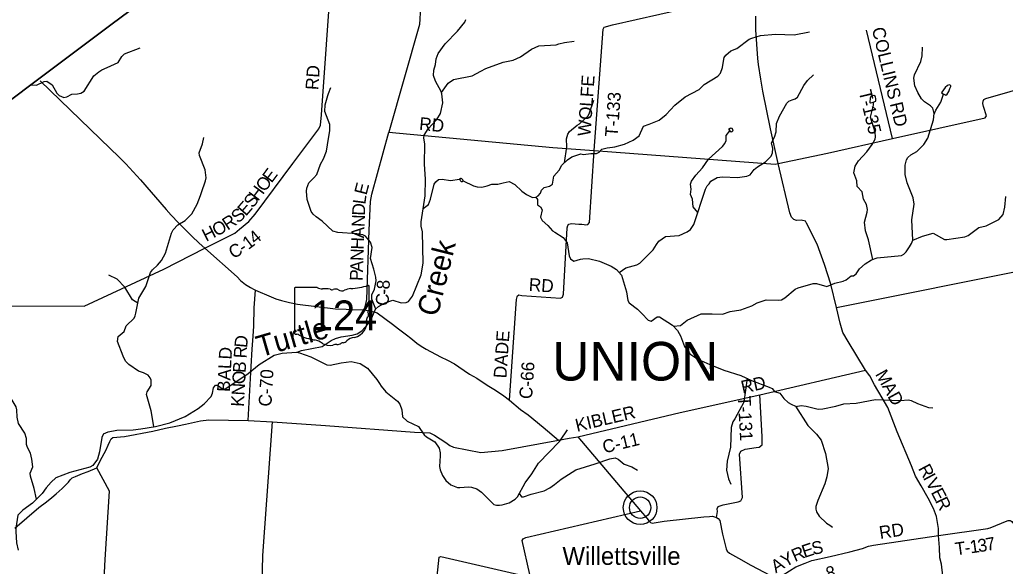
# Model space of a CAD drawing. Extents: x 1525783 to 1900577, y 218250 to 627376.
# Drawn here: x 1612574 to 1635582, y 457419 to 470168 of the extents above; entities that cross this region are included whole.
import ezdxf

# ---------------------------------------------------------------- set-up
doc = ezdxf.new("R2010")
doc.units = 0
for name, color, linetype in [('GM_X_Adjacent_County', 7, 'Continuous'), ('GM_X_County', 7, 'Continuous'), ('GM_X_County_Road', 7, 'Continuous'), ('GM_X_County_Road_Text', 7, 'Continuous'), ('GM_X_Minor_Lake', 7, 'Continuous'), ('GM_X_Minor_River', 7, 'Continuous'), ('GM_X_Minor_River_Text', 7, 'Continuous'), ('GM_X_State_Location', 7, 'Continuous'), ('GM_X_State_Route', 7, 'Continuous'), ('GM_X_State_Shield', 7, 'Continuous'), ('GM_X_Township', 7, 'Continuous'), ('GM_X_Township_Road', 7, 'Continuous'), ('GM_X_Township_Road_Text', 7, 'Continuous'), ('GM_X_Township_ROW', 7, 'Continuous'), ('GM_X_Township_Text', 7, 'Continuous'), ('GM_X_Unincorporated', 7, 'Continuous'), ('GM_X_Unincorporated_Location', 7, 'Continuous'), ('GM_X_Unincorporated_Text', 7, 'Continuous')]:
    doc.layers.add(name, color=color, linetype=linetype)

msp = doc.modelspace()

# ---------------------------------------------------------------- linework, layer by layer
at = {"layer": 'GM_X_Adjacent_County'}
msp.add_lwpolyline([(1655741, 500852), (1648788, 495779), (1648023, 495203), (1647133, 494533), (1640676, 489672), (1638042, 487688), (1635644, 485883), (1633819, 484508), (1633505, 484272), (1633248, 484078), (1631413, 482696), (1628958, 480847), (1628919, 480818), (1621997, 475474), (1621966, 475451), (1620523, 474378), (1618604, 472952), (1614700, 470050), (1612987, 468763), (1608261, 465210)], dxfattribs=at)
at = {"layer": 'GM_X_County'}
msp.add_lwpolyline([(1608261, 465210), (1612987, 468763), (1614700, 470050), (1618604, 472952), (1620523, 474378), (1621966, 475451), (1621997, 475474), (1628919, 480818), (1628958, 480847), (1631413, 482696), (1633248, 484078), (1633505, 484272), (1633819, 484508), (1635644, 485883), (1638042, 487688), (1640676, 489672), (1647133, 494533), (1648023, 495203), (1648788, 495779), (1655741, 500852)], dxfattribs=at)
at = {"layer": 'GM_X_County_Road'}
for points in [[(1622004, 471684), (1621903, 470055), (1621187, 467545)], [(1616894, 464836), (1617238, 465007), (1617593, 465191), (1617706, 465283), (1617919, 465465), (1618070, 465630), (1618950, 466813), (1619555, 467622), (1619599, 467705), (1619622, 467949), (1619849, 471240)], [(1630283, 466815), (1630102, 467622), (1629921, 468502), (1629876, 468780), (1629821, 469126), (1629805, 469261), (1629760, 469933), (1629755, 470250)], [(1630283, 466815), (1631433, 467057), (1632947, 467397), (1635111, 467882), (1635142, 467924), (1635076, 468146), (1635061, 468212), (1635063, 468268), (1635080, 468310), (1635129, 468331), (1637455, 468999)], [(1620622, 463404), (1620675, 463645), (1620734, 465258), (1620762, 465929), (1620796, 466099), (1621187, 467545), (1625016, 467185), (1625986, 467115), (1630208, 466799), (1630283, 466815)], [(1624010, 461291), (1624166, 463538), (1624175, 463644), (1624178, 463674), (1624183, 463702), (1624191, 463730), (1624226, 463747), (1624296, 463739), (1625201, 463673), (1625244, 463698), (1625270, 463763), (1625357, 465316), (1625369, 465370), (1625391, 465400), (1625454, 465416), (1625626, 465399), (1625694, 465398), (1625748, 465388), (1625792, 465385), (1625840, 465392), (1625877, 465437), (1625986, 467115)], [(1634156, 456927), (1634091, 457468), (1634051, 457616), (1634047, 457854), (1634025, 458139), (1634023, 458298), (1633974, 458583), (1633905, 458766), (1633783, 459005), (1633615, 459292), (1633487, 459524), (1633389, 459761), (1633061, 460556), (1632838, 461121), (1632704, 461351), (1632531, 461650), (1632419, 461865), (1632316, 461996), (1631915, 462664), (1631789, 462870), (1631728, 463092), (1631640, 463455), (1631508, 463999), (1631362, 464458), (1631188, 464934), (1630945, 465419), (1630916, 465466), (1630817, 465495), (1630708, 465487), (1630645, 465507), (1630588, 465559), (1630551, 465664), (1630283, 466815)], [(1608202, 458990), (1608203, 458990), (1608370, 458987), (1609398, 458988), (1609760, 458989), (1609917, 458994), (1610645, 459107), (1610906, 459152), (1611190, 459203), (1611367, 459238), (1611441, 459254), (1611469, 459292), (1611494, 459398), (1611652, 461938), (1611750, 463493), (1614078, 463489), (1615942, 464351), (1616894, 464836)], [(1617906, 460822), (1617979, 462079), (1617998, 462483), (1618026, 462783), (1618040, 463017), (1618046, 463448), (1618078, 463862)], [(1625600, 460439), (1627995, 461006), (1629849, 461416), (1632316, 461996)], [(1612458, 458311), (1613021, 458786), (1613200, 458924), (1613322, 459027), (1613427, 459109), (1613566, 459235), (1613714, 459380), (1613749, 459432), (1613795, 459480), (1613877, 459514), (1614038, 459583), (1614172, 459627), (1614377, 459716), (1614460, 459892), (1614588, 460121), (1614641, 460246), (1614678, 460331), (1614709, 460394), (1614746, 460421), (1615017, 460448), (1615683, 460569), (1615980, 460643), (1616258, 460696), (1616441, 460735), (1616794, 460808), (1616991, 460837), (1617906, 460822), (1618474, 460787), (1619714, 460700), (1621787, 460547), (1622151, 460529), (1622258, 460476), (1622520, 460303), (1622614, 460233), (1622701, 460200), (1623337, 460071), (1623839, 460122), (1625153, 460358)]]:
    msp.add_lwpolyline(points, dxfattribs=at)
at = {"layer": 'GM_X_Minor_Lake'}
for points in [[(1634103, 468477), (1634096, 468462), (1634133, 468441)], [(1634133, 468441), (1634160, 468424), (1634190, 468409), (1634224, 468433), (1634261, 468492), (1634286, 468562), (1634297, 468580), (1634309, 468612), (1634308, 468636), (1634268, 468646), (1634231, 468631), (1634179, 468588), (1634140, 468532), (1634103, 468477)], [(1632420, 468247), (1632419, 468237), (1632428, 468230), (1632434, 468231), (1632494, 468247)], [(1632494, 468247), (1632556, 468267), (1632563, 468318), (1632554, 468375), (1632510, 468403), (1632466, 468396), (1632442, 468378), (1632429, 468337), (1632420, 468247)], [(1629154, 467574), (1629182, 467552), (1629206, 467559), (1629220, 467573), (1629226, 467603), (1629205, 467632), (1629175, 467638), (1629157, 467632), (1629122, 467607)], [(1629122, 467607), (1629135, 467597), (1629154, 467574)], [(1622923, 466412), (1622918, 466430), (1622896, 466454), (1622880, 466464), (1622866, 466465), (1622850, 466459), (1622842, 466449), (1622853, 466425), (1622863, 466411), (1622883, 466398), (1622911, 466396)], [(1622911, 466396), (1622923, 466412)]]:
    msp.add_lwpolyline(points, dxfattribs=at)
at = {"layer": 'GM_X_Minor_River'}
for points in [[(1619049, 462411), (1619153, 462449), (1619637, 462542), (1619845, 462687), (1619946, 462733), (1620075, 462773), (1620332, 462807), (1620450, 462844), (1620560, 462908), (1620716, 463082), (1620790, 463201), (1620880, 463416), (1620949, 463481), (1621108, 463566), (1621288, 463630), (1621481, 463566), (1621597, 463571), (1621648, 463596), (1621742, 463717), (1621944, 464214), (1621990, 464488), (1621974, 465221), (1621946, 465349), (1621945, 465456), (1622037, 466057), (1622047, 466451), (1622025, 466800), (1622030, 467267), (1622010, 467413), (1622015, 467479), (1622110, 467624), (1622313, 467843), (1622396, 467980), (1622450, 468233), (1622431, 468438), (1622414, 468496), (1622283, 468737), (1622233, 468870), (1622239, 468990), (1622280, 469127), (1622298, 469257), (1622344, 469384), (1622503, 469608), (1622794, 469904), (1622966, 470110), (1622989, 470173)], [(1622923, 466413), (1623170, 466296), (1623253, 466268), (1623359, 466265), (1623484, 466291), (1623595, 466335), (1623737, 466331), (1623862, 466363), (1623998, 466391), (1624133, 466323), (1624297, 466170), (1624404, 466092), (1624543, 466022), (1624621, 466027), (1624676, 466060), (1624729, 466123), (1624758, 466189), (1624817, 466254), (1624943, 466288), (1625008, 466329), (1625045, 466517), (1625171, 466657), (1625227, 466774), (1625358, 466900), (1625463, 466971), (1625670, 467038), (1625736, 467025), (1625910, 467048), (1626036, 467044), (1626103, 467081), (1626166, 467146), (1626287, 467182), (1626413, 467198), (1626463, 467206), (1626691, 467262), (1626896, 467355), (1627034, 467463), (1627136, 467684), (1627270, 467728), (1627504, 467828), (1627665, 467958), (1627870, 468177), (1628111, 468367), (1628432, 468541), (1628556, 468657), (1628870, 468848), (1628935, 468921), (1628979, 469051), (1628988, 469105), (1629021, 469285), (1629060, 469340), (1629171, 469442), (1629316, 469496), (1629606, 469714), (1629665, 469739), (1629864, 469802), (1630221, 469835), (1630651, 469816), (1631010, 469888)], [(1622421, 468470), (1622577, 468688), (1622698, 468774), (1623138, 468861), (1623340, 468966), (1623453, 469029), (1623858, 469181), (1624097, 469227), (1624264, 469304), (1624521, 469485), (1624695, 469562), (1625100, 469584), (1625156, 469603), (1625289, 469639), (1625519, 469667)], [(1614613, 469050), (1614869, 469173), (1614957, 469310), (1615022, 469369), (1615389, 469509)], [(1633420, 465025), (1633397, 465500), (1633451, 465868), (1633433, 466012), (1633295, 466367), (1633244, 466554), (1633243, 466774), (1633273, 466900), (1633304, 466951), (1633375, 467014), (1633517, 467098), (1633679, 467258), (1633776, 467403), (1633905, 467833), (1633925, 467979), (1633893, 468106), (1633834, 468163), (1633695, 468253), (1633628, 468324), (1633538, 468470), (1633469, 468625), (1633447, 468803), (1633465, 468883), (1633614, 469195), (1633642, 469329), (1633649, 469525)], [(1612838, 468649), (1612969, 468641), (1613143, 468731), (1613207, 468733), (1613330, 468649), (1613438, 468453), (1613493, 468399), (1613605, 468357), (1613673, 468370), (1613788, 468431), (1613926, 468437), (1613999, 468455), (1614077, 468498), (1614306, 468857), (1614424, 468954), (1614494, 468997), (1614613, 469050)], [(1626566, 464274), (1626721, 464382), (1626980, 464448), (1627051, 464491), (1627362, 464804), (1627436, 464927), (1627492, 465005), (1627650, 465114), (1627970, 465135), (1628156, 465223), (1628233, 465278), (1628313, 465394), (1628584, 466213), (1628621, 466291), (1628668, 466342), (1628707, 466402), (1628854, 466487), (1628977, 466506), (1629329, 466484), (1629550, 466515), (1629628, 466552), (1629722, 466672), (1629795, 466737), (1629981, 466856), (1630114, 466989), (1630151, 467060), (1630156, 467166), (1630127, 467299), (1630195, 467428), (1630235, 467553), (1630242, 467744), (1630312, 467915), (1630479, 468221), (1630532, 468266), (1630607, 468299), (1630677, 468326), (1630728, 468361), (1630876, 468631), (1630968, 468750), (1631104, 468884)], [(1620885, 463420), (1620795, 463647), (1620795, 463753), (1620859, 463885), (1620892, 464078), (1620886, 464166), (1620839, 464353), (1620765, 464601), (1620802, 464851), (1620763, 464981), (1620647, 465119), (1620583, 465154), (1620441, 465175), (1620003, 465202), (1619880, 465234), (1619633, 465468), (1619494, 465568), (1619421, 465633), (1619376, 465692), (1619287, 465976), (1619272, 466172), (1619279, 466238), (1619323, 466362), (1619439, 466478), (1619512, 466561), (1619596, 466800), (1619668, 466923), (1619735, 467104), (1619782, 467400), (1619811, 467580), (1619815, 467724), (1619700, 468030), (1619702, 468182), (1619763, 468397), (1619784, 468449), (1619835, 468589)], [(1625288, 466833), (1625346, 467203), (1625335, 467389), (1625367, 467495), (1625408, 467564), (1625586, 467706), (1625639, 467737), (1625834, 467918), (1625871, 467974), (1625980, 468288)], [(1632490, 464578), (1632385, 465031), (1632316, 465244), (1632297, 465449), (1632361, 465682), (1632366, 465744), (1632340, 465859), (1632272, 465984), (1632238, 466157), (1632122, 466281), (1632114, 466409), (1632043, 466598), (1632078, 466754), (1632152, 466879), (1632351, 467084), (1632476, 467256), (1632542, 467380), (1632555, 467435), (1632543, 467546), (1632436, 467892), (1632509, 468175), (1632503, 468250)], [(1633923, 467964), (1633958, 468055), (1634079, 468245), (1634143, 468435)], [(1628405, 465673), (1628295, 465807), (1628278, 465982), (1628230, 466093), (1628248, 466219), (1628233, 466333), (1628259, 466403), (1628359, 466541), (1628514, 466717), (1628657, 466915), (1628980, 467208), (1629037, 467278), (1629066, 467349), (1629068, 467471), (1629150, 467579)], [(1615708, 460676), (1615645, 461046), (1615537, 461424), (1615552, 461490), (1615642, 461637), (1615640, 461761), (1615623, 461814), (1615576, 461874), (1615467, 461932), (1615349, 461970), (1615118, 462124), (1615041, 462205), (1614988, 462318), (1614858, 462663), (1614872, 462778), (1615016, 462898), (1615062, 463024), (1615245, 463205), (1615266, 463261), (1615281, 463321), (1615356, 463672), (1615521, 463942), (1615628, 464273), (1615671, 464334), (1615791, 464440), (1615887, 464555), (1615978, 464726), (1616121, 465192), (1616154, 465270), (1616264, 465384), (1616440, 465484), (1616589, 465639), (1616714, 465868), (1616794, 466069), (1616817, 466134), (1616911, 466411), (1616926, 466483), (1616907, 466670), (1616774, 467000), (1616767, 467066), (1616843, 467276), (1616875, 467423)], [(1621992, 465761), (1622114, 465858), (1622164, 465981), (1622249, 466332), (1622286, 466390), (1622351, 466441), (1622435, 466451), (1622631, 466420), (1622844, 466452)], [(1624621, 466027), (1624658, 465976), (1624660, 465850), (1624728, 465807), (1624769, 465734), (1624734, 465560), (1624773, 465482), (1624901, 465371), (1625015, 465244), (1625067, 465211), (1625261, 465087), (1625353, 464966), (1625404, 464659), (1625433, 464590), (1625510, 464539), (1625665, 464579), (1625717, 464592), (1625854, 464602), (1626107, 464536), (1626379, 464417), (1626506, 464343), (1626620, 464211), (1626736, 463819), (1626771, 463620), (1626798, 463562), (1626996, 463420), (1627095, 463315), (1627248, 463158), (1627318, 463137), (1627452, 463235), (1627506, 463234), (1627811, 463047), (1627933, 462919), (1627970, 462846), (1628001, 462792), (1628094, 462548), (1628221, 462372), (1628407, 462247), (1628681, 462128), (1629014, 461995), (1629410, 461871), (1629659, 461755), (1630070, 461600), (1630138, 461563), (1630197, 461494), (1630318, 461456), (1630413, 461335), (1630517, 461241), (1630581, 461202), (1630688, 461152), (1630975, 460703), (1631178, 460502), (1631284, 460362), (1631387, 460048), (1631446, 459701), (1631419, 459505), (1631368, 459339), (1631204, 458957), (1631161, 458812), (1631160, 458750), (1631175, 458687), (1631238, 458584), (1631410, 458424), (1631483, 458374), (1631550, 458333)], [(1627834, 463023), (1628003, 463032), (1628159, 463158), (1628482, 463307), (1628738, 463305), (1628978, 463303), (1629157, 463359), (1629408, 463403), (1629662, 463491), (1629787, 463563), (1630000, 463632), (1630289, 463624), (1630357, 463636), (1630432, 463681), (1630679, 463886), (1630744, 463913), (1631100, 464012), (1631176, 464014), (1631413, 463947), (1631602, 464022), (1631799, 464073), (1631866, 464100), (1631983, 464196), (1632037, 464195), (1632100, 464238), (1632176, 464361), (1632308, 464475), (1632462, 464567), (1632592, 464615), (1633162, 464671), (1633212, 464696), (1633271, 464755), (1633345, 464874), (1633389, 464951), (1633420, 465025), (1633649, 465120), (1633897, 465186), (1634159, 465038), (1634217, 465041), (1634636, 465104), (1634717, 465137), (1634968, 465319), (1635137, 465359), (1635433, 465510), (1635529, 465623), (1635574, 465799), (1635594, 466043)], [(1615332, 463558), (1615209, 463634), (1615024, 463932), (1614849, 464119), (1614652, 464206)], [(1614528, 460511), (1614638, 460557), (1614843, 460590), (1615226, 460598), (1615400, 460625), (1615745, 460682), (1616079, 460765), (1616434, 460916), (1616743, 461099), (1616883, 461205), (1617040, 461381), (1617077, 461456), (1617099, 461584), (1617142, 461642), (1617200, 461645), (1617261, 461590), (1617331, 461553), (1617383, 461566), (1617907, 461912), (1618161, 462124), (1618516, 462343), (1618699, 462388), (1619034, 462415), (1619106, 462394), (1619369, 462302), (1619744, 462114), (1619820, 462112), (1620075, 462161), (1620308, 462195), (1620519, 462150), (1620692, 462043), (1620914, 461779), (1620971, 461686), (1621010, 461623), (1621118, 461485), (1621395, 461273), (1621451, 461202), (1621493, 461071), (1621509, 460905), (1621621, 460801), (1621886, 460682), (1622019, 460488), (1622074, 460435), (1622262, 460318), (1622368, 460172), (1622391, 460068), (1622391, 459992), (1622377, 459746), (1622388, 459671), (1622440, 459538), (1622524, 459421), (1622637, 459317), (1622794, 459258), (1622846, 459258), (1623047, 459272), (1623121, 459265), (1623248, 459223), (1623357, 459151), (1623645, 458859), (1623704, 458842), (1623775, 458845), (1623833, 458854), (1624002, 458901), (1624139, 458981), (1624194, 459040), (1624377, 459368), (1624531, 459578), (1624687, 459824), (1625174, 460331), (1625315, 460535), (1625358, 460602)], [(1629553, 461804), (1629478, 461245), (1629270, 460860), (1629225, 460788), (1629181, 460655), (1629169, 460198), (1629090, 459869), (1629075, 459661), (1629118, 459460), (1629178, 459337)], [(1612965, 458985), (1612912, 459232), (1612825, 459522), (1612818, 459594), (1612878, 459738), (1612860, 459918), (1612824, 460061), (1612753, 460186), (1612732, 460258), (1612732, 460400), (1612696, 460521), (1612546, 460753), (1612514, 460898), (1612510, 461072), (1612493, 461139), (1612348, 461369), (1612303, 461483)], [(1630690, 461149), (1630816, 461168), (1630932, 461156), (1631211, 461084), (1631326, 461092), (1631623, 461152), (1631814, 461209), (1632102, 461224), (1632554, 461308), (1633130, 461287), (1633323, 461302), (1633385, 461289), (1633530, 461218), (1633786, 461122), (1633890, 461115)], [(1614528, 460511), (1614489, 460421), (1614435, 460085), (1614389, 459918), (1614281, 459771), (1614214, 459733), (1614091, 459701), (1613742, 459609), (1613417, 459479), (1613308, 459384), (1613188, 459245), (1613098, 459120), (1612869, 458888), (1612647, 458731), (1612531, 458608), (1612483, 458310), (1612480, 458228), (1612499, 457963), (1612539, 457792)], [(1624236, 459115), (1624288, 459041), (1624338, 459038), (1624511, 459099), (1624819, 459177), (1624952, 459245), (1625055, 459323), (1625214, 459451), (1625559, 459672), (1626008, 459807), (1626350, 459922), (1626473, 459948), (1626542, 459919), (1626685, 459800), (1626862, 459738), (1626999, 459657)]]:
    msp.add_lwpolyline(points, dxfattribs=at)
at = {"layer": 'GM_X_State_Route'}
for points in [[(1613051, 468742), (1614682, 467165), (1614885, 466973), (1615050, 466807), (1615393, 466432), (1615993, 465741), (1616109, 465612), (1616278, 465430), (1616595, 465117), (1616764, 464955), (1616894, 464836), (1617647, 464169), (1617727, 464088), (1617847, 463995), (1617962, 463924), (1618044, 463879), (1618078, 463862), (1618134, 463834), (1618386, 463724), (1618554, 463658), (1618688, 463619), (1618870, 463568), (1619055, 463530), (1619942, 463428), (1620195, 463416), (1620196, 463415)], [(1620196, 463415), (1620343, 463408), (1620622, 463404), (1620770, 463373), (1620852, 463357), (1620918, 463328), (1621273, 463069), (1621415, 462959), (1621416, 462959)], [(1621416, 462959), (1621602, 462815), (1621704, 462737), (1621842, 462627), (1621947, 462550), (1622065, 462485), (1622395, 462304), (1622559, 462227), (1622721, 462141), (1622822, 462074), (1623074, 461904), (1623242, 461806), (1623487, 461644), (1623681, 461524), (1623876, 461395), (1624010, 461291), (1624263, 461079), (1624441, 460949), (1624790, 460660), (1625153, 460358), (1625402, 460404), (1625600, 460439), (1627063, 458711), (1627214, 458540), (1627268, 458471), (1627297, 458439), (1627337, 458425), (1627622, 458469), (1628547, 458572), (1628676, 458583), (1628750, 458587), (1628818, 458568), (1628838, 458555), (1628878, 458530), (1628918, 458485), (1628982, 458164), (1629062, 457822), (1629089, 457772), (1629147, 457723), (1629357, 457607), (1629641, 457443), (1630245, 457127)]]:
    msp.add_lwpolyline(points, dxfattribs=at)
at = {"layer": 'GM_X_State_Shield'}
for p, q in [((1618992, 463905), (1618992, 462849)), ((1619518, 463924), (1619009, 463924)), ((1620732, 463397), (1620732, 463950)), ((1620732, 463397), (1620732, 463397))]:
    msp.add_line(p, q, dxfattribs=at)
for centre, major_axis, start_param, end_param in [((1619012, 463908), (20.2, 0), 1.712693, 3.28349), ((1619640, 464046), (196, 0), 4.042523, 4.731795), ((1619705, 463330), (702, 0), 1.404758, 1.657858), ((1619864, 463913), (56.4, 0), 3.836095, 5.185415), ((1619947, 463791), (117, 0), 0.950623, 2.079405), ((1620098, 463959), (141, 0), 4.081561, 5.145723), ((1620347, 463601), (371, 0), 1.699011, 2.107814), ((1620112, 465364), (1845, 0), 4.814394, 5.042369), ((1620713, 463952), (19.4, 0), 6.141152, 7.989035), ((1620711, 463395), (20.7, 0), 5.05454, 6.418171), ((1620215, 463095), (462, 0), 5.101752, 6.440018), ((1620801, 463166), (131, 0), 2.387724, 3.262537), ((1620727, 463357), (30, 0), 1.883978, 3.671073), ((1620537, 463287), (180, 0), 5.934695, 6.695948), ((1619012, 462847), (20.3, 0), 3.00124, 4.508301), ((1619015, 462955), (155, 0), 4.665946, 4.897461), ((1619047, 462788), (56, 0), 0.519207, 1.627899), ((1619753, 463737), (1333, 0), 4.195997, 4.488961), ((1619356, 462374), (417, 0), 0.823519, 1.323587), ((1620410, 462552), (253, 0), 1.647645, 2.488434), ((1619807, 462783), (265, 0), 4.026481, 4.996735), ((1619960, 462417), (217, 0), 1.495662, 1.94098), ((1619979, 462703), (141, 0), 4.691044, 5.507374), ((1620107, 462601), (39.7, 0), 1.147584, 2.315152), ((1620090, 462746), (149, 0), 4.937069, 5.64225)]:
    msp.add_ellipse(centre, major_axis=major_axis, ratio=0.8, start_param=start_param, end_param=end_param, dxfattribs=at)
at = {"layer": 'GM_X_Township'}
msp.add_lwpolyline([(1608261, 465210), (1612987, 468763), (1614700, 470050), (1618604, 472952)], dxfattribs=at)
at = {"layer": 'GM_X_Township_Road'}
for points in [[(1625986, 467115), (1626191, 469948), (1626218, 469993), (1626412, 470050), (1629729, 470804)], [(1632947, 467397), (1632345, 469928)], [(1628838, 458555), (1628861, 458700), (1628853, 458758), (1628878, 458814), (1628992, 458853), (1629346, 458925), (1629410, 458948), (1629449, 459026), (1629376, 460034), (1629410, 460106), (1629511, 460151), (1629766, 460186), (1629838, 460197), (1629906, 460251), (1629906, 460445), (1629849, 461416)], [(1617815, 449927), (1618232, 456993), (1618232, 456999), (1618252, 457669), (1618474, 460787)], [(1614509, 456256), (1614509, 456258), (1614512, 456513), (1614569, 457580), (1614670, 459174), (1614377, 459716)], [(1621313, 450458), (1620985, 451909), (1620897, 452216), (1620907, 452345), (1621082, 453728), (1622245, 456450), (1622365, 457634), (1622405, 457643), (1624328, 457204), (1624406, 457184), (1624462, 457194), (1624479, 457230), (1624304, 458019), (1624327, 458062), (1624388, 458091), (1627063, 458711)], [(1634025, 458139), (1635172, 458301), (1635199, 458307), (1635226, 458317), (1635626, 458479), (1635649, 458485), (1635673, 458486), (1635692, 458483), (1635712, 458476), (1635735, 458462), (1635752, 458443), (1635763, 458423), (1635771, 458393), (1635866, 457610), (1635879, 457574), (1635900, 457547), (1635921, 457531)], [(1630245, 457127), (1630696, 457403), (1630913, 457495), (1631069, 457557), (1631494, 457645), (1631956, 457753), (1632251, 457833), (1632385, 457891), (1632508, 457910), (1634025, 458139)]]:
    msp.add_lwpolyline(points, dxfattribs=at)
at = {"layer": 'GM_X_Township_ROW'}
msp.add_lwpolyline([(1631640, 463455), (1636265, 464384), (1638255, 464844), (1638708, 465005)], dxfattribs=at)
at = {"layer": 'GM_X_Unincorporated'}
for radius in [393, 249]:
    msp.add_circle((1627058, 458786), radius, dxfattribs=at)
at = {"layer": 'GM_X_Unincorporated_Location'}
msp.add_line((1627058, 458786), (1627058, 458786), dxfattribs=at)

# ---------------------------------------------------------------- texts
at = {"layer": 'GM_X_County_Road_Text'}
for s, rotation, p in [('RD', 86.0551, (1619543, 468521)), ('RD', 354.5354, (1621890, 467599)), ('E', 53.2694, (1618453, 466344)), ('O', 53.2671, (1618295, 466133)), ('E', 75.5324, (1620669, 466063)), ('H', 53.2671, (1618137, 465921)), ('E', 48.9574, (1617853, 465571)), ('S', 53.0185, (1618015, 465758)), ('L', 82.5475, (1620642, 465850)), ('S', 41.1384, (1617669, 465406)), ('D', 87.6626, (1620632, 465593)), ('O', 27.2497, (1617163, 465105)), ('R', 33.4369, (1617428, 465244)), ('N', 87.9669, (1620623, 465330)), ('H', 26.8786, (1616926, 464985)), ('4', 39.5722, (1618073, 464914)), ('A', 87.9669, (1620613, 465066)), ('1', 36.7845, (1617912, 464794)), ('H', 87.9669, (1620604, 464802)), ('C', 28.2043, (1617551, 464583)), ('-', 33.4947, (1617794, 464715)), ('N', 87.9669, (1620594, 464538)), ('A', 87.9677, (1620585, 464275)), ('P', 87.9659, (1620578, 464072)), ('8', 87.9014, (1621207, 463873)), ('RD', 356.0551, (1624451, 463844)), ('-', 87.7326, (1621202, 463749)), ('C', 83.79, (1621173, 463481)), ('D', 84.9995, (1617882, 462507)), ('DADE', 86.0205, (1623934, 461797)), ('BALD', 86.9998, (1617479, 461480)), ('R', 86.3952, (1617866, 462263)), ('B', 86.9133, (1617848, 461925)), ('C-70', 86.5731, (1618448, 461138)), ('C-66', 85.8656, (1624532, 461312)), ('M', 299.2911, (1632537, 461900)), ('O', 86.9272, (1617834, 461661)), ('RD', 12.737, (1629449, 461444)), ('N', 86.9258, (1617820, 461398)), ('A', 299.2883, (1632696, 461616)), ('K', 86.9277, (1617805, 461134)), ('D', 298.773, (1632825, 461386)), ('KIBLER', 13.2952, (1625583, 460554)), ('C-11', 13.4563, (1626219, 460051)), ('R', 297.9074, (1633541, 459703)), ('I', 297.9082, (1633656, 459486)), ('V', 297.9076, (1633714, 459377)), ('E', 297.7995, (1633837, 459144)), ('R', 295.3536, (1633940, 458948))]:
    msp.add_text(s, height=300, rotation=rotation, dxfattribs=at).set_placement(p)
at = {"layer": 'GM_X_Minor_River_Text'}
for s, rotation, p in [('Creek', 75.9834, (1622327, 463221)), ('Turtle', 16.1812, (1618183, 462290))]:
    msp.add_text(s, height=500, rotation=rotation, dxfattribs=at).set_placement(p)
at = {"layer": 'GM_X_State_Location'}
msp.add_text('124', height=1, rotation=0, dxfattribs=at).set_placement((1619489, 463234))
for s in ['s', 'r']:
    msp.add_text(s, height=1, dxfattribs=at).set_placement((1619842, 463307))
at = {"layer": 'GM_X_State_Shield'}
msp.add_text('124', height=696.1, dxfattribs=at).set_placement((1619367, 462923))
at = {"layer": 'GM_X_Township_Road_Text'}
for s, rotation, p in [('COLLINS', 283.4452, (1632465, 469957)), ('WOLFE', 86.0001, (1625897, 467443)), ('T-133', 85.7741, (1626534, 467427)), ('T-135', 283.627, (1632157, 468491)), ('RD', 283.4372, (1632883, 468210)), ('T-131', 273.0864, (1629336, 461383)), ('RD', 8.8966, (1632662, 458052)), ('7', 10.3372, (1635152, 457774)), ('R', 23.3744, (1630670, 457515)), ('E', 18.4634, (1630890, 457610)), ('S', 12.9432, (1631096, 457679)), ('T', 8.0059, (1634429, 457670)), ('1', 8.0906, (1634774, 457719)), ('3', 8.37, (1634958, 457745)), ('Y', 29.4114, (1630448, 457389)), ('-', 8.0157, (1634652, 457701)), ('A', 31.4557, (1630225, 457252)), ('8', 12.0846, (1631426, 457099))]:
    msp.add_text(s, height=300, rotation=rotation, dxfattribs=at).set_placement(p)
at = {"layer": 'GM_X_Township_Text'}
msp.add_text('UNION', height=900, rotation=0, dxfattribs=at).set_placement((1625005, 461752))
at = {"layer": 'GM_X_Unincorporated_Text'}
msp.add_text('Willettsville', height=417, rotation=0, dxfattribs=at).set_placement((1625244, 457451))

doc.saveas('drawing.dxf')
